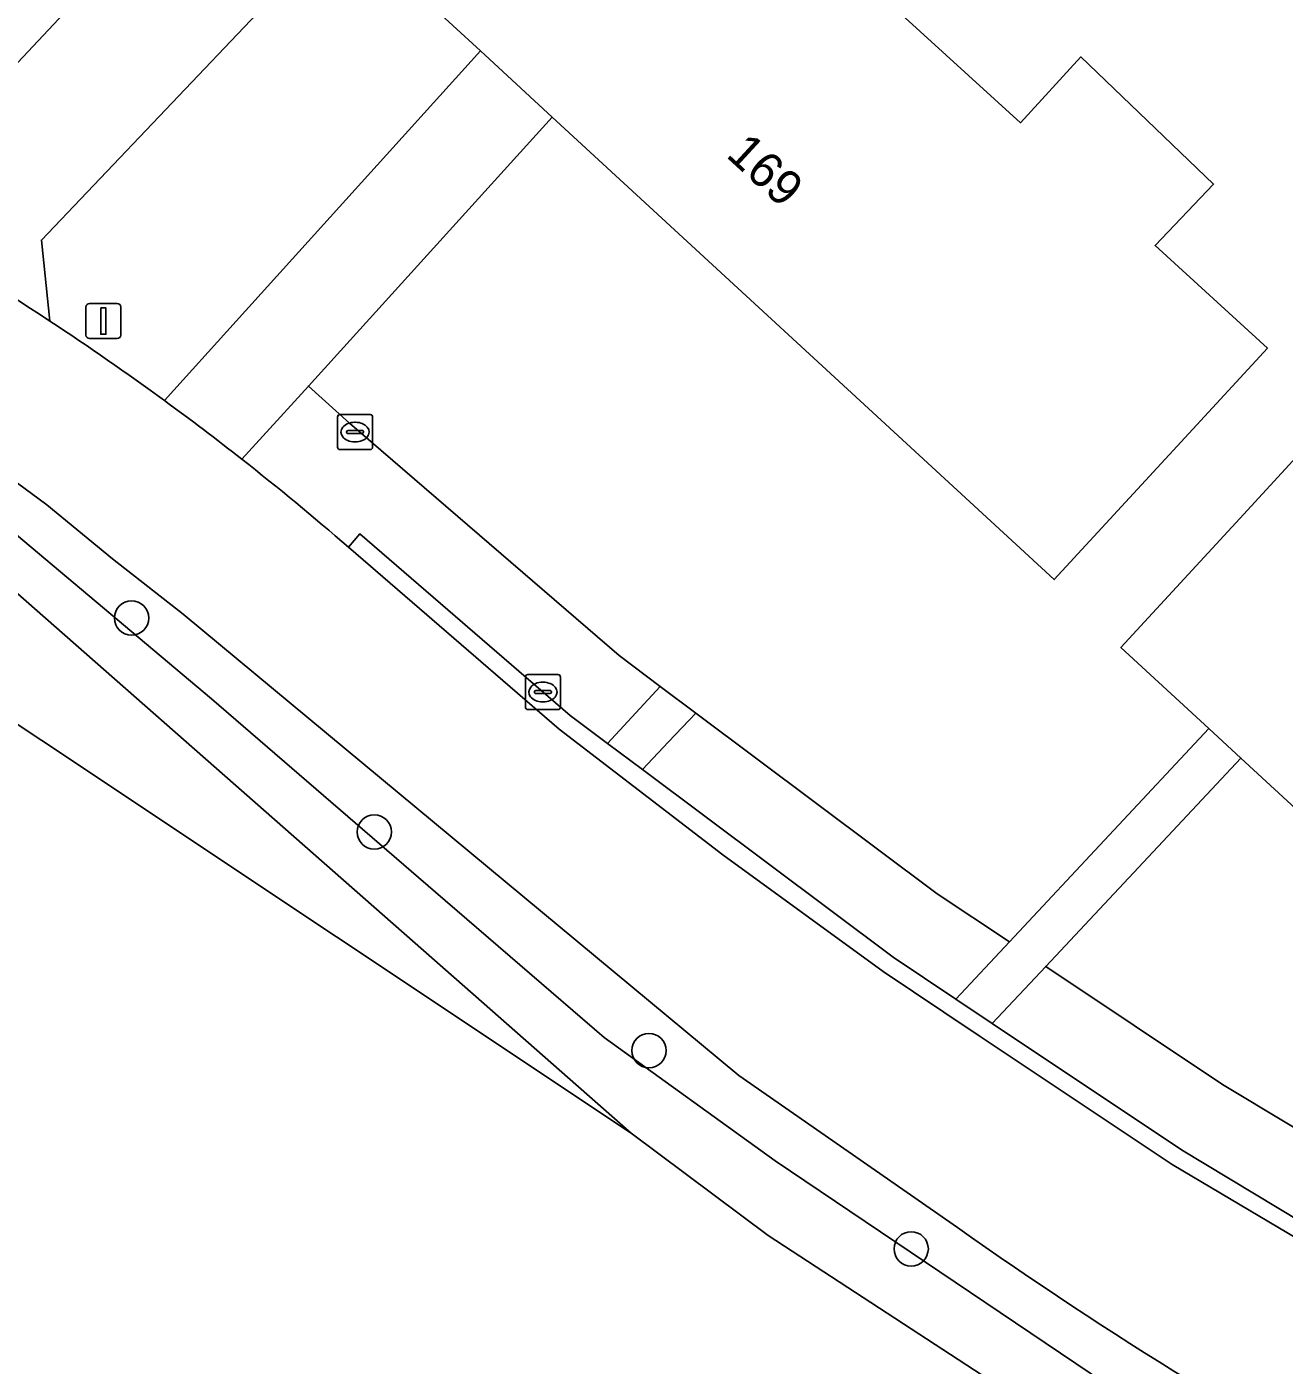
# Model space of a CAD drawing. Extents: x 160203 to 161530, y 379528 to 381797.
# Drawn here: x 160857.86 to 160893.7, y 381439 to 381477.14 of the extents above; entities that cross this region are included whole.
import ezdxf

# ---------------------------------------------------------------- set-up
doc = ezdxf.new("R2010")
doc.units = 0
for name, color, linetype in [('IMGEO_Berm_groen', 7, 'Continuous'), ('IMGEO_Boom', 7, 'Continuous'), ('IMGEO_Erf', 7, 'Continuous'), ('IMGEO_Grasland_agrarisch', 7, 'Continuous'), ('IMGEO_Grasland_overig', 7, 'Continuous'), ('IMGEO_Groenvoorziening', 7, 'Continuous'), ('IMGEO_Kolk', 7, 'Continuous'), ('IMGEO_Lichtmast', 7, 'Continuous'), ('IMGEO_Pand', 7, 'Continuous'), ('IMGEO_Pand_nummerreeks', 7, 'Continuous'), ('IMGEO_Parkeervlak_open', 7, 'Continuous'), ('IMGEO_Rijbaan_lokaal_gesloten', 7, 'Continuous'), ('IMGEO_Rijbaan_lokaal_open', 7, 'Continuous'), ('IMGEO_Rioolput', 7, 'Continuous'), ('IMGEO_Voetpad_open', 7, 'Continuous'), ('IMGEO_Waterloop', 7, 'Continuous')]:
    doc.layers.add(name, color=color, linetype=linetype)

msp = doc.modelspace()

# ---------------------------------------------------------------- linework, layer by layer
at = {"layer": 'IMGEO_Berm_groen'}
msp.add_lwpolyline([(160884.389, 381442.919), (160878.159, 381447.251), (160862.316, 381460.398), (160860.301, 381461.982), (160858.436, 381463.516), (160847.256, 381471.764), (160846.694, 381471.054), (160852.001, 381467.339), (160863.128, 381457.99), (160869.51, 381452.479), (160874.317, 381448.335), (160879.191, 381444.823), (160891.171, 381436.75)], dxfattribs=at)
msp.add_arc((160952.119, 381538.443), 117.099, 234.66177, 242.38961, dxfattribs=at)
at = {"layer": 'IMGEO_Boom'}
for centre in [(160860.847, 381460.291), (160867.765, 381454.194), (160875.594, 381447.965), (160883.069, 381442.313)]:
    msp.add_circle(centre, 0.489, dxfattribs=at)
at = {"layer": 'IMGEO_Erf'}
for points in [[(160853.366, 381477.791), (160852.468, 381475.687), (160849.017, 381474.358), (160852.239, 381472.497), (160854.749, 381473.091), (160856.568, 381475.028), (160878.497, 381498.378)], [(160878.246, 381481.639), (160886.18, 381474.404), (160887.903, 381476.28), (160891.688, 381472.657), (160890.019, 381470.905), (160893.224, 381467.982), (160890.536, 381465.063), (160887.148, 381461.385), (160872.838, 381474.565), (160865.887, 381466.901), (160867.061, 381465.849), (160874.741, 381459.219), (160875.912, 381458.343), (160876.93, 381457.581), (160883.813, 381452.43), (160885.867, 381451.059), (160891.553, 381457.141), (160889.045, 381459.451), (160892.433, 381463.129), (160893.945, 381464.771)], [(160870.791, 381476.451), (160866.855, 381480.076), (160859.578, 381472.429), (160858.276, 381471.06), (160858.52, 381468.754)], [(160861.784, 381466.49), (160863.833, 381468.756), (160870.791, 381476.451)], [(160900.148, 381449.225), (160892.469, 381456.298), (160886.906, 381450.365), (160891.946, 381447), (160905.254, 381438.997)]]:
    msp.add_lwpolyline(points, dxfattribs=at)
msp.add_arc((160814.111, 381401.245), 80.807, 53.84533, 56.66219, dxfattribs=at)
at = {"layer": 'IMGEO_Grasland_agrarisch'}
msp.add_lwpolyline([(160890.073, 381435.469), (160878.992, 381442.693), (160875.085, 381445.607), (160849.884, 381462.395)], dxfattribs=at)
at = {"layer": 'IMGEO_Grasland_overig'}
for points in [[(160852.727, 381465.266), (160848.029, 381468.736), (160845.97, 381470.138), (160845.7, 381469.057), (160845.467, 381468.034), (160845.956, 381467.034), (160849.884, 381462.395), (160875.085, 381445.607), (160870.581, 381449.572)], [(160876.93, 381457.581), (160876.155, 381456.761), (160875.41, 381455.972), (160882.554, 381450.625), (160884.344, 381449.43), (160885.867, 381451.059), (160883.813, 381452.43)]]:
    msp.add_lwpolyline(points, close=True, dxfattribs=at)
for points in [[(160875.912, 381458.343), (160874.741, 381459.219), (160867.061, 381465.849), (160865.887, 381466.901), (160863.995, 381464.815)], [(160867.027, 381462.312), (160867.354, 381462.69), (160873.353, 381457.511), (160874.414, 381456.717), (160875.912, 381458.343)]]:
    msp.add_lwpolyline(points, dxfattribs=at)
msp.add_arc((160813.868, 381401.006), 81.144, 49.07117, 51.84759, dxfattribs=at)
at = {"layer": 'IMGEO_Groenvoorziening'}
msp.add_lwpolyline([(160904.841, 381437.986), (160905.254, 381438.997), (160891.946, 381447), (160886.906, 381450.365), (160885.38, 381448.738), (160890.774, 381445.137), (160899.001, 381440.181), (160906.67, 381435.562)], dxfattribs=at)
at = {"layer": 'IMGEO_Kolk'}
for p, q in [((160872.072, 381457.756), (160872.072, 381458.608)), ((160872.147, 381458.682), (160872.999, 381458.682)), ((160873.073, 381458.608), (160873.073, 381457.756)), ((160872.331, 381458.176), (160872.331, 381458.188)), ((160872.769, 381458.139), (160872.371, 381458.139)), ((160872.374, 381458.225), (160872.772, 381458.225)), ((160872.56, 381458.462), (160872.585, 381458.462)), ((160872.815, 381458.188), (160872.815, 381458.176)), ((160872.583, 381457.902), (160872.558, 381457.902)), ((160872.999, 381457.682), (160872.147, 381457.682))]:
    msp.add_line(p, q, dxfattribs=at)
for points in [[(160872.072, 381457.756), (160872.072, 381458.608)], [(160872.147, 381458.682), (160872.999, 381458.682)], [(160873.073, 381458.608), (160873.073, 381457.756)], [(160872.999, 381457.682), (160872.147, 381457.682)]]:
    msp.add_lwpolyline(points, dxfattribs=at)
for centre, radius, start, end in [((160872.149, 381458.606), 0.0765, 91.552, 178.448), ((160872.149, 381458.606), 0.0765, 91.552, 178.448), ((160872.997, 381458.606), 0.0765, 1.552, 88.448), ((160872.997, 381458.606), 0.0765, 1.552, 88.448), ((160872.371, 381458.185), 0.0403, 85.8775, 175.7526), ((160872.368, 381458.175), 0.0366, 178.938, 274.7102), ((160872.772, 381458.182), 0.043, 264.8664, 352.4533), ((160872.776, 381458.187), 0.0386, 1.7309, 96.639), ((160872.149, 381457.758), 0.0765, 181.552, 268.448), ((160872.149, 381457.758), 0.0765, 181.552, 268.448), ((160872.997, 381457.758), 0.0765, 271.552, 358.448), ((160872.997, 381457.758), 0.0765, 271.552, 358.448)]:
    msp.add_arc(centre, radius, start, end, dxfattribs=at)
for centre, major_axis, ratio, start_param, end_param in [((160872.559, 381458.182), (-0.387, 0.002), 0.722429, 4.712389, 7.853982), ((160872.584, 381458.182), (-0.39, 0.002), 0.717154, 1.570796, 4.712389)]:
    msp.add_ellipse(centre, major_axis=major_axis, ratio=ratio, start_param=start_param, end_param=end_param, dxfattribs=at)
at = {"layer": 'IMGEO_Lichtmast'}
for p, q in [((160859.649, 381469.255), (160860.439, 381469.255)), ((160860.439, 381469.255), (160859.649, 381469.255)), ((160859.549, 381468.355), (160859.549, 381469.155)), ((160859.549, 381469.155), (160859.549, 381468.355)), ((160860.539, 381469.155), (160860.539, 381468.355)), ((160860.539, 381468.355), (160860.539, 381469.155)), ((160860.439, 381468.255), (160859.649, 381468.255)), ((160859.649, 381468.255), (160860.439, 381468.255))]:
    msp.add_line(p, q, dxfattribs=at)
msp.add_lwpolyline([(160859.969, 381469.13), (160860.119, 381469.13), (160860.119, 381468.38), (160859.969, 381468.38), (160859.969, 381469.13)], dxfattribs=at)
for centre, start, end in [((160859.649, 381469.155), 90, 180), ((160859.649, 381469.155), 90, 180), ((160860.439, 381469.155), 0, 90), ((160860.439, 381469.155), 360, 90), ((160859.649, 381468.355), 180, 270), ((160859.649, 381468.355), 180, 270), ((160860.439, 381468.355), 270, 0), ((160860.439, 381468.355), 270, 0)]:
    msp.add_arc(centre, 0.1, start, end, dxfattribs=at)
at = {"layer": 'IMGEO_Pand'}
for points in [[(160893.224, 381467.982), (160890.019, 381470.905), (160891.688, 381472.657), (160887.903, 381476.28), (160886.18, 381474.404), (160878.246, 381481.639), (160872.838, 381486.57), (160866.855, 381480.076), (160870.791, 381476.451), (160872.838, 381474.565), (160887.148, 381461.385), (160890.536, 381465.063)], [(160903.579, 381455.898), (160893.945, 381464.771), (160892.433, 381463.129), (160889.045, 381459.451), (160891.553, 381457.141), (160892.469, 381456.298), (160900.148, 381449.225), (160900.45, 381449.555), (160901.621, 381448.484), (160907.474, 381454.694), (160904.833, 381457.134)]]:
    msp.add_lwpolyline(points, close=True, dxfattribs=at)
at = {"layer": 'IMGEO_Parkeervlak_open'}
msp.add_lwpolyline([(160858.52, 381468.754), (160858.276, 381471.06), (160859.578, 381472.429), (160866.855, 381480.076), (160872.838, 381486.57), (160878.246, 381481.639), (160886.709, 381490.688), (160878.497, 381498.378), (160856.568, 381475.028), (160854.749, 381473.091), (160852.239, 381472.497), (160852.454, 381472.373)], dxfattribs=at)
msp.add_arc((160814.331, 381401.58), 80.406, 56.66204, 61.69701, dxfattribs=at)
at = {"layer": 'IMGEO_Rijbaan_lokaal_gesloten'}
for points in [[(160852.454, 381472.373), (160852.239, 381472.497), (160849.017, 381474.358), (160847.256, 381471.764), (160858.436, 381463.516), (160860.301, 381461.982), (160862.316, 381460.398), (160878.159, 381447.251), (160884.389, 381442.919)], [(160897.849, 381434.679), (160902.709, 381432.115), (160904.063, 381431.29), (160906.67, 381435.562), (160899.001, 381440.181), (160898.776, 381439.814), (160890.508, 381444.714), (160885.033, 381448.369), (160883.998, 381449.06), (160882.268, 381450.215), (160877.698, 381453.546), (160873.036, 381457.125), (160867.027, 381462.312)]]:
    msp.add_lwpolyline(points, dxfattribs=at)
for centre, radius, start, end in [((160814.331, 381401.58), 80.406, 56.66204, 61.69701), ((160814.111, 381401.245), 80.807, 53.84533, 56.66219), ((160814.901, 381402.307), 79.482, 51.85349, 53.85314), ((160813.868, 381401.006), 81.144, 49.07117, 51.84759), ((160952.119, 381538.443), 117.099, 234.66177, 242.38961)]:
    msp.add_arc(centre, radius, start, end, dxfattribs=at)
at = {"layer": 'IMGEO_Rijbaan_lokaal_open'}
msp.add_lwpolyline([(160875.41, 381455.972), (160874.414, 381456.717), (160873.353, 381457.511), (160867.354, 381462.69), (160867.027, 381462.312), (160873.036, 381457.125), (160877.698, 381453.546), (160882.268, 381450.215), (160883.998, 381449.06), (160885.033, 381448.369), (160890.508, 381444.714), (160898.776, 381439.814), (160899.001, 381440.181), (160890.774, 381445.137), (160885.38, 381448.738), (160884.344, 381449.43), (160882.554, 381450.625)], close=True, dxfattribs=at)
at = {"layer": 'IMGEO_Rioolput'}
for p, q in [((160866.717, 381465.164), (160866.717, 381466.016)), ((160866.792, 381466.09), (160867.644, 381466.09)), ((160867.205, 381465.87), (160867.23, 381465.87)), ((160867.718, 381466.016), (160867.718, 381465.164)), ((160866.976, 381465.584), (160866.976, 381465.596)), ((160867.414, 381465.547), (160867.016, 381465.547)), ((160867.019, 381465.633), (160867.417, 381465.633)), ((160867.46, 381465.596), (160867.46, 381465.584)), ((160867.644, 381465.09), (160866.792, 381465.09)), ((160867.228, 381465.31), (160867.203, 381465.31))]:
    msp.add_line(p, q, dxfattribs=at)
for points in [[(160866.717, 381465.164), (160866.717, 381466.016)], [(160866.792, 381466.09), (160867.644, 381466.09)], [(160867.718, 381466.016), (160867.718, 381465.164)], [(160867.644, 381465.09), (160866.792, 381465.09)]]:
    msp.add_lwpolyline(points, dxfattribs=at)
for centre, radius, start, end in [((160866.794, 381466.014), 0.0765, 91.552, 178.448), ((160866.794, 381466.014), 0.0765, 91.552, 178.448), ((160867.642, 381466.014), 0.0765, 1.552, 88.448), ((160867.642, 381466.014), 0.0765, 1.552, 88.448), ((160867.016, 381465.593), 0.0403, 85.8775, 175.7526), ((160867.013, 381465.583), 0.0366, 178.938, 274.7102), ((160867.417, 381465.59), 0.043, 264.8664, 352.4533), ((160867.421, 381465.595), 0.0386, 1.7309, 96.639), ((160866.794, 381465.166), 0.0765, 181.552, 268.448), ((160866.794, 381465.166), 0.0765, 181.552, 268.448), ((160867.642, 381465.166), 0.0765, 271.552, 358.448), ((160867.642, 381465.166), 0.0765, 271.552, 358.448)]:
    msp.add_arc(centre, radius, start, end, dxfattribs=at)
for centre, major_axis, ratio, start_param, end_param in [((160867.204, 381465.59), (-0.387, 0.002), 0.722429, 4.712389, 7.853982), ((160867.229, 381465.59), (-0.39, 0.002), 0.717154, 1.570796, 4.712389)]:
    msp.add_ellipse(centre, major_axis=major_axis, ratio=ratio, start_param=start_param, end_param=end_param, dxfattribs=at)
at = {"layer": 'IMGEO_Voetpad_open'}
msp.add_lwpolyline([(160863.995, 381464.815), (160865.887, 381466.901), (160872.838, 381474.565), (160870.791, 381476.451), (160863.833, 381468.756), (160861.784, 381466.49)], dxfattribs=at)
for points in [[(160876.93, 381457.581), (160875.912, 381458.343), (160874.414, 381456.717), (160875.41, 381455.972), (160876.155, 381456.761)], [(160892.469, 381456.298), (160891.553, 381457.141), (160885.867, 381451.059), (160884.344, 381449.43), (160885.38, 381448.738), (160886.906, 381450.365)]]:
    msp.add_lwpolyline(points, close=True, dxfattribs=at)
msp.add_arc((160814.901, 381402.307), 79.482, 51.85349, 53.85314, dxfattribs=at)
at = {"layer": 'IMGEO_Waterloop'}
msp.add_lwpolyline([(160852.001, 381467.339), (160846.694, 381471.054), (160845.97, 381470.138), (160848.029, 381468.736), (160852.727, 381465.266), (160870.581, 381449.572), (160875.085, 381445.607), (160878.992, 381442.693), (160890.073, 381435.469), (160896.402, 381431.864), (160899.711, 381430.263), (160907.02, 381426.384), (160907.929, 381427.645), (160904.059, 381429.909), (160903.816, 381430.038), (160903.426, 381430.245), (160891.171, 381436.75), (160879.191, 381444.823), (160874.317, 381448.335), (160869.51, 381452.479), (160863.128, 381457.99)], close=True, dxfattribs=at)

# ---------------------------------------------------------------- texts
at = {"layer": 'IMGEO_Pand_nummerreeks'}
msp.add_text('169', height=1, rotation=317.3532, dxfattribs=at).set_placement((160877.762, 381473.457))

doc.saveas('drawing.dxf')
